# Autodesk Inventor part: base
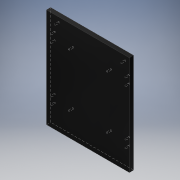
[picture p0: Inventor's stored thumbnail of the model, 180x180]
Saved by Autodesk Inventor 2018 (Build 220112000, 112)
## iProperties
Created: 2023-12
Part Number: base
Material: Generic
Document SubType Name: Modeling
Designer: DDUGKY
Density: 1 g/cm^3
Appearance: Default
Author: DDUGKY
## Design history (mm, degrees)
sketch "Sketch1"
  geometry: L1 (250, 300)-(-250, 300); L2 (-250, 300)-(-250, -300); L3 (-250, -300)-(250, -300); L4 (250, -300)-(250, 300); L5 (250, 300)-(-250, -300); L6 (-250, 300)-(250, -300); 1 further point
  constraints: 12 end point, 2 midpoint, 2 parallel, 1 horizontal, 1 perpendicular
  dimensions: "d0" = 500 distance of L3.end L2.end; "d1" = 600 distance of L2.end L1.end
extrude "Extrusion1" new body sketch "Sketch1" distance "d2" = 25; taper "d3" = 0 deg
sketch "Sketch4"
  geometry: L1 (250, 300)-(250, -300) reference; L2 (-250, -200)-(250, -200); L3 (250, -200)-(250, 200); L4 (250, 200)-(-250, 200); L5 (-250, 200)-(-250, -200); L6 (-250, -200)-(250, 200); L7 (250, -200)-(-250, 200); L8 (240, -200)-(210, -200); L9 (210, -200)-(210, -125); L10 (210, -125)-(240, -125); L11 (240, -125)-(240, -200); L12 (225, -200)-(225, -185); L13 (225, -125)-(225, -140); L14 (-13.928, 0)-(0, 0); L15 (0, 0)-(0, -17.808); L16 (250, -200)-(240, -200); C1 r 3.75 at (225, -185); C2 r 3.75 at (225, -140); C3 r 3.75 at (-225, -140); C4 r 3.75 at (-225, -185); C5 r 3.75 at (-225, 185); C6 r 3.75 at (-225, 140); C7 r 3.75 at (225, 140); C8 r 3.75 at (225, 185)
  constraints: 30 end point, 8 centre point, 6 symmetric about line, 4 midpoint, 4 parallel, 4 perpendicular, 3 horizontal, 2 coincident, 2 point on line, 1 vertical, 6 other
  dimensions: "d24" = 400 distance of L3.end L2.end; "d26" = 30 distance of L9.end L10.end; "d27" = 75 distance of L8.end L9.end; "d28" = 15 distance of L12.start L12.end; "d29" = 15 distance of L13.start L13.end; "d30" = 7.5 diameter of C1; "d31" = 7.5 diameter of C2; "d34" = 10 distance of L2.end L16.end
extrude "Extrusion5" cut sketch "Sketch4" stored distance "d35" = 776; taper "d36" = 0 deg
sketch "Sketch5"
  geometry: L1 (0, 247.422)-(-200, 247.422); L2 (0, 247.422)-(200, 247.422); C1 r 3.75 at (-200, 247.422); C2 r 3.75 at (200, 247.422); 1 further point
  constraints: 4 end point, 2 centre point, 2 coincident, 2 horizontal
  dimensions: "d37" = 200 distance of L1.start L1.end; "d38" = 200 distance of L1.start L2.end; "d39" = 7.5 diameter of C1; "d40" = 7.5 diameter of C2
extrude "Extrusion6" cut sketch "Sketch5" distance "d41" = 53.25; taper "d42" = 0 deg
sketch "Sketch6"
  geometry: L1 (-115, -160)-(115, -160); L2 (115, -160)-(115, 160); L3 (115, 160)-(-115, 160); L4 (-115, 160)-(-115, -160); L5 (-115, -160)-(115, 160); L6 (115, -160)-(-115, 160); C1 r 3.75 at (-115, -160); C2 r 3.75 at (-115, 160); C3 r 3.75 at (115, 160); C4 r 3.75 at (115, -160); 1 further point
  constraints: 12 end point, 4 centre point, 4 coincident, 2 midpoint, 2 parallel, 1 horizontal, 1 perpendicular
  dimensions: "d46" = 230 distance of L3.end L2.end; "d47" = 320 distance of L2.end L1.end; "d48" = 7.5 diameter of C1; "d49" = 7.5 diameter of C2; "d50" = 7.5 diameter of C3; "d51" = 7.5 diameter of C4
extrude "Extrusion7" cut sketch "Sketch6" stored distance "d52" = 69.25; taper "d53" = 0 deg
body "Solid1"
